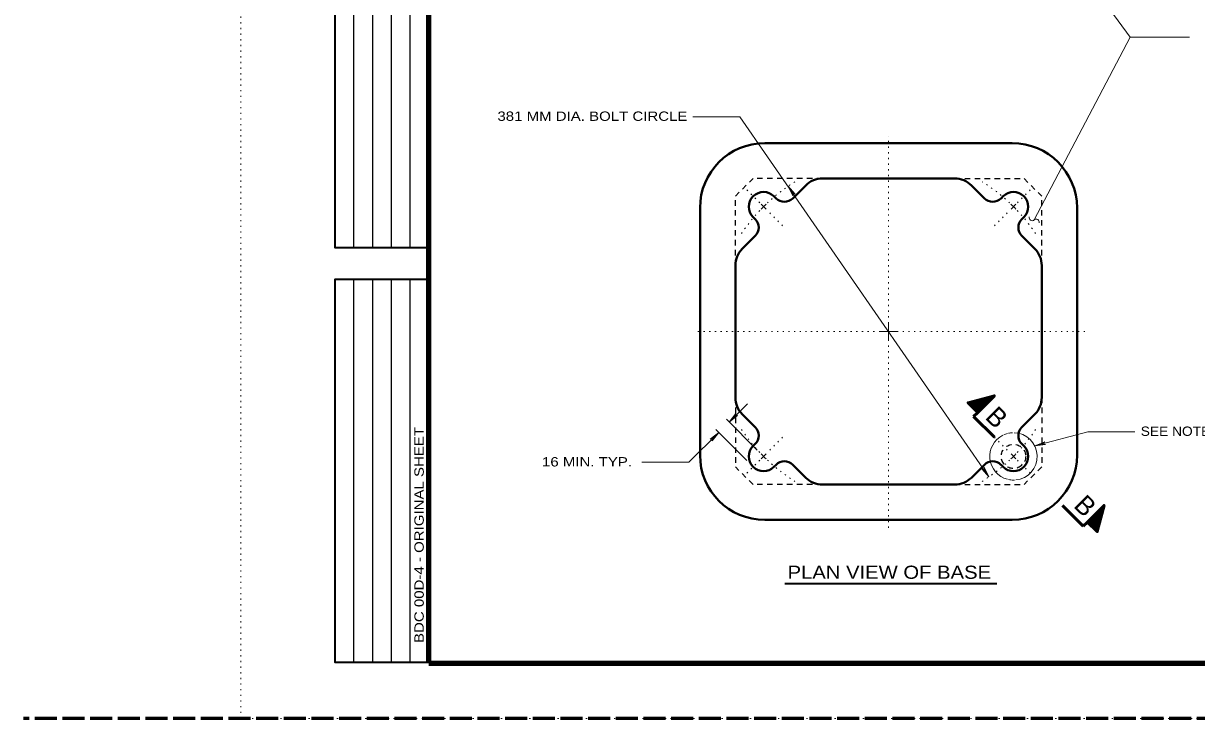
# Model space of a CAD drawing. Extents: x 312583 to 312854, y 144419 to 144597.
# Drawn here: x 312583.5 to 312678.9, y 144418.6 to 144475.2 of the extents above; entities that cross this region are included whole.
import ezdxf
from ezdxf.enums import TextEntityAlignment as Align

# ---------------------------------------------------------------- set-up
doc = ezdxf.new("R2010")
doc.units = 0
doc.header["$LTSCALE"] = 0.3
for name, pattern in [('DOTTED', [1.5, 0.3, -1.2]), ('LONG_DASHED', [7.5, 6, -1.5]), ('SHORT_DASHED', [2.7, 1.5, -1.2])]:
    doc.linetypes.add(name, pattern=pattern)
for name, color, linetype, lineweight in [('1', 7, 'Continuous', 40), ('2', 7, 'Continuous', 13), ('62', 7, 'DOTTED', 13), ('63', 7, 'LONG_DASHED', 60)]:
    doc.layers.add(name, color=color, linetype=linetype, lineweight=lineweight)

msp = doc.modelspace()

# ---------------------------------------------------------------- linework, layer by layer
at = {"layer": '1', "lineweight": 25}
for p, q in [((312610.4087, 144456.901), (312610.4087, 144488.1192)), ((312611.9315, 144456.901), (312611.9315, 144488.1192)), ((312613.4543, 144456.901), (312613.4543, 144488.1192)), ((312614.9772, 144456.901), (312614.9772, 144488.1192)), ((312610.4087, 144423.1446), (312610.4087, 144454.3629)), ((312611.9315, 144423.1446), (312611.9315, 144454.3629)), ((312613.4543, 144423.1446), (312613.4543, 144454.3629)), ((312614.9772, 144423.1446), (312614.9772, 144454.3629))]:
    msp.add_line(p, q, dxfattribs=at)
at = {"layer": '1'}
for p, q in [((312643.821, 144465.4263), (312653.8873, 144465.4263)), ((312663.946, 144465.4263), (312653.8873, 144465.4263)), ((312646.0903, 144460.9336), (312647.1483, 144461.9916)), ((312648.5053, 144462.5513), (312653.8873, 144462.5513)), ((312659.2693, 144462.5513), (312653.8873, 144462.5513)), ((312660.6187, 144461.9916), (312661.6767, 144460.9336)), ((312644.5647, 144461.1023), (312644.7333, 144460.9336)), ((312663.2023, 144461.1023), (312663.0337, 144460.9336)), ((312638.554, 144460.1516), (312638.554, 144450.0929)), ((312669.2207, 144460.1516), (312669.2207, 144450.0929)), ((312642.8703, 144459.4079), (312643.039, 144459.2393)), ((312664.8967, 144459.4079), (312664.728, 144459.2393)), ((312641.9887, 144456.8319), (312643.039, 144457.8823)), ((312664.728, 144457.8823), (312665.7783, 144456.8319)), ((312641.429, 144455.4749), (312641.429, 144450.0929)), ((312666.3457, 144455.4749), (312666.3457, 144450.0929)), ((312638.554, 144440.0266), (312638.554, 144450.0929)), ((312641.429, 144444.7109), (312641.429, 144450.0929)), ((312666.3457, 144444.7109), (312666.3457, 144450.0929)), ((312669.2207, 144440.0266), (312669.2207, 144450.0929)), ((312643.039, 144442.3036), (312641.9887, 144443.3539)), ((312665.7783, 144443.3539), (312664.728, 144442.3036)), ((312642.8703, 144440.7779), (312643.039, 144440.9466)), ((312664.8967, 144440.7779), (312664.728, 144440.9466)), ((312644.5647, 144439.0836), (312644.7333, 144439.2523)), ((312647.1483, 144438.1943), (312646.0903, 144439.2523)), ((312661.6767, 144439.2523), (312660.6187, 144438.1943)), ((312663.2023, 144439.0836), (312663.0337, 144439.2523)), ((312648.5053, 144437.6346), (312653.8873, 144437.6346)), ((312659.2693, 144437.6346), (312653.8873, 144437.6346)), ((312643.821, 144434.7596), (312653.8873, 144434.7596)), ((312663.946, 144434.7596), (312653.8873, 144434.7596))]:
    msp.add_line(p, q, dxfattribs=at)
at = {"layer": '1', "linetype": 'SHORT_DASHED', "lineweight": 25}
for p, q in [((312648.5053, 144462.5513), (312642.8627, 144462.5513)), ((312666.3457, 144455.4749), (312666.3457, 144461.1099)), ((312641.429, 144444.7109), (312641.429, 144439.0683)), ((312659.2693, 144437.6346), (312664.9043, 144437.6346))]:
    msp.add_line(p, q, dxfattribs=at)
at = {"layer": '1', "lineweight": 13}
for p, q in [((312645.7147, 144461.9149), (312646.1133, 144461.1406)), ((312645.7147, 144461.9149), (312646.2897, 144461.2633)), ((312646.1133, 144461.1406), (312646.052, 144461.4319)), ((312646.2897, 144461.2633), (312646.052, 144461.4319)), ((312643.9283, 144460.0519), (312643.522, 144460.4583)), ((312663.8463, 144460.0519), (312664.245, 144460.4583)), ((312643.9283, 144440.1339), (312643.522, 144439.7276)), ((312663.8463, 144440.1339), (312664.245, 144439.7276))]:
    msp.add_line(p, q, dxfattribs=at)
at = {"layer": '1', "linetype": 'DOTTED', "lineweight": 13}
for p, q in [((312643.407, 144460.5733), (312642.2877, 144461.6849)), ((312664.36, 144460.5733), (312665.4793, 144461.6849)), ((312645.27, 144458.7026), (312644.0357, 144459.9446)), ((312662.497, 144458.7026), (312663.7313, 144459.9446)), ((312645.27, 144441.4833), (312644.0357, 144440.2413)), ((312662.497, 144441.4833), (312663.7313, 144440.2413)), ((312643.407, 144439.6126), (312642.2877, 144438.4933)), ((312664.36, 144439.6126), (312665.4793, 144438.4933))]:
    msp.add_line(p, q, dxfattribs=at)
at = {"layer": '1', "lineweight": 158}
msp.add_line((312616.5, 144423.0846), (312849, 144423.0846), dxfattribs=at)
msp.add_lwpolyline([(312616.5, 144423.1446), (312616.5, 144585.0846), (312849, 144585.0846)], dxfattribs=at)
at = {"layer": '1', "lineweight": 35}
for points in [[(312616.5, 144456.901), (312608.8858, 144456.901), (312608.8858, 144488.1192), (312616.5, 144488.1192)], [(312616.5, 144423.1446), (312608.8858, 144423.1446), (312608.8858, 144454.3629), (312616.5, 144454.3629)]]:
    msp.add_lwpolyline(points, dxfattribs=at)
at = {"layer": '1', "linetype": 'SHORT_DASHED', "lineweight": 25}
for points in [[(312641.429, 144455.4749), (312641.429, 144461.1099), (312642.8627, 144462.5513)], [(312659.2693, 144462.5513), (312664.9043, 144462.5513), (312666.3457, 144461.1099)], [(312666.3457, 144444.7109), (312666.3457, 144439.0683), (312664.9043, 144437.6346)], [(312648.5053, 144437.6346), (312642.8627, 144437.6346), (312641.429, 144439.0683)]]:
    msp.add_lwpolyline(points, dxfattribs=at)
msp.add_circle((312664.0476, 144439.9269), 0.9909, dxfattribs=at)
at = {"layer": '1'}
for centre, radius, start, end in [((312643.821, 144460.1535), 5.2708, 90, 180), ((312663.946, 144460.1535), 5.2708, 0, 90), ((312648.5019, 144460.6327), 1.9167, 90, 135), ((312659.2651, 144460.6327), 1.9167, 45, 90), ((312643.7194, 144460.2551), 1.1979, 45, 225), ((312645.4138, 144461.6104), 0.9583, 225, 315), ((312662.3532, 144461.6104), 0.9583, 225, 315), ((312664.0476, 144460.2551), 1.1979, 315, 135), ((312642.3641, 144458.5608), 0.9583, 315, 45), ((312665.4029, 144458.5608), 0.9583, 135, 225), ((312643.3418, 144455.4726), 1.9167, 135, 180), ((312664.4252, 144455.4726), 1.9167, 0, 45), ((312643.3418, 144444.7094), 1.9167, 180, 225), ((312664.4252, 144444.7094), 1.9167, 315, 0), ((312642.3641, 144441.6213), 0.9583, 315, 45), ((312665.4029, 144441.6213), 0.9583, 135, 225), ((312643.821, 144440.0285), 5.2708, 180, 270), ((312643.7194, 144439.9269), 1.1979, 135, 315), ((312664.0476, 144439.9269), 1.1979, 225, 45), ((312663.946, 144440.0285), 5.2708, 270, 0), ((312645.4138, 144438.5716), 0.9583, 45, 135), ((312662.3532, 144438.5716), 0.9583, 45, 135), ((312648.5019, 144439.5493), 1.9167, 225, 270), ((312659.2651, 144439.5493), 1.9167, 270, 315)]:
    msp.add_arc(centre, radius, start, end, dxfattribs=at)
at = {"layer": '1', "linetype": 'DOTTED', "lineweight": 13}
for start, end in [(121.96733, 133.24434), (46.75566, 58.03267), (136.75599, 146.30781), (33.69219, 43.24401), (213.69219, 223.24401), (316.75599, 326.30781), (226.75566, 238.03268), (301.96733, 313.24434)]:
    msp.add_arc((312653.8835, 144450.091), 14.375, start, end, dxfattribs=at)
at = {"layer": '1', "lineweight": 13}
for centre, radius, start, end in [((312653.8835, 144450.091), 14.375, 133.83351, 136.1341), ((312653.8835, 144450.091), 14.375, 43.8659, 46.16649), ((312664.0476, 144439.9269), 1.9285, 92.27696, 101.90639), ((312664.0476, 144439.9269), 1.9285, 275.24598, 88.67448), ((312664.0476, 144439.9269), 1.9285, 116.79454, 255.14924), ((312664.0476, 144439.9269), 1.9285, 104.7083, 114.31631), ((312653.8835, 144450.091), 14.375, 223.8659, 226.16649), ((312653.8835, 144450.091), 14.375, 313.83351, 316.1341), ((312664.0476, 144439.9269), 1.9285, 257.50819, 264.13093), ((312664.0476, 144439.9269), 1.9285, 266.0607, 272.6285)]:
    msp.add_arc(centre, radius, start, end, dxfattribs=at)
at = {"layer": '2'}
for p, q in [((312673.5293, 144474.0513), (312668.178, 144481.4036)), ((312673.5293, 144474.0513), (312665.7247, 144459.1779)), ((312673.5293, 144474.0513), (312678.3517, 144474.0513)), ((312641.797, 144467.5806), (312637.9637, 144467.5806)), ((312641.797, 144467.5806), (312662.0523, 144438.2709)), ((312653.8873, 144450.0929), (312653.8873, 144450.8596)), ((312653.8873, 144450.0929), (312653.1207, 144450.0929)), ((312653.8873, 144450.0929), (312654.654, 144450.0929)), ((312653.8873, 144450.0929), (312653.8873, 144449.3263)), ((312640.9307, 144442.7253), (312642.418, 144444.2126)), ((312643.2077, 144440.4406), (312640.693, 144442.9553)), ((312640.9307, 144442.7253), (312641.4673, 144443.4076)), ((312640.9307, 144442.7253), (312641.613, 144443.2619)), ((312641.4673, 144443.4076), (312641.3447, 144443.1393)), ((312641.613, 144443.2619), (312641.3447, 144443.1393)), ((312637.6493, 144439.4439), (312640.0797, 144441.8743)), ((312640.0797, 144441.8743), (312639.3897, 144441.3376)), ((312640.0797, 144441.8743), (312639.543, 144441.1843)), ((312642.3567, 144439.5973), (312639.8497, 144442.1043)), ((312665.7783, 144440.7779), (312670.087, 144441.9356)), ((312670.087, 144441.9356), (312673.9203, 144441.9356)), ((312639.3897, 144441.3376), (312639.6657, 144441.4603)), ((312639.543, 144441.1843), (312639.6657, 144441.4603)), ((312665.7783, 144440.7779), (312666.591, 144441.1076)), ((312665.7783, 144440.7779), (312666.6447, 144440.9006)), ((312666.591, 144441.1076), (312666.3457, 144440.9313)), ((312666.6447, 144440.9006), (312666.3457, 144440.9313)), ((312637.6493, 144439.4439), (312633.816, 144439.4439)), ((312661.6537, 144439.0376), (312661.7227, 144438.7539)), ((312662.0523, 144438.2709), (312661.6537, 144439.0376)), ((312661.4773, 144438.9226), (312661.7227, 144438.7539)), ((312662.0523, 144438.2709), (312661.4773, 144438.9226))]:
    msp.add_line(p, q, dxfattribs=at)
at = {"layer": '2', "linetype": 'DOTTED'}
for p, q in [((312653.8873, 144451.2429), (312653.8873, 144465.9629)), ((312652.7373, 144450.0929), (312638.0787, 144450.0929)), ((312655.0373, 144450.0929), (312669.8417, 144450.0929)), ((312653.8873, 144448.9429), (312653.8873, 144433.9853))]:
    msp.add_line(p, q, dxfattribs=at)
at = {"layer": '2', "lineweight": 35}
for p, q in [((312661.9757, 144444.3429), (312661.876, 144444.7033)), ((312661.991, 144444.3583), (312661.899, 144444.7033)), ((312662.014, 144444.3813), (312661.922, 144444.7109)), ((312662.037, 144444.4043), (312661.945, 144444.7186)), ((312662.0523, 144444.4196), (312661.968, 144444.7186)), ((312662.0753, 144444.4426), (312661.9987, 144444.7339)), ((312662.0907, 144444.4579), (312662.014, 144444.7416)), ((312662.1137, 144444.4809), (312662.037, 144444.7416)), ((312662.1367, 144444.4963), (312662.06, 144444.7569)), ((312662.152, 144444.5193), (312662.083, 144444.7569)), ((312662.1673, 144444.5346), (312662.106, 144444.7646)), ((312662.1903, 144444.5576), (312662.1367, 144444.7723)), ((312662.2057, 144444.5729), (312662.152, 144444.7723)), ((312662.2287, 144444.5959), (312662.175, 144444.7799)), ((312662.2517, 144444.6189), (312662.2057, 144444.7876)), ((312662.267, 144444.6343), (312662.2287, 144444.7876)), ((312662.29, 144444.6573), (312662.244, 144444.7953)), ((312662.3053, 144444.6726), (312662.2747, 144444.8029)), ((312662.3207, 144444.6879), (312662.2977, 144444.8106)), ((312662.3437, 144444.7109), (312662.3207, 144444.8106)), ((312662.3667, 144444.7339), (312662.336, 144444.8259)), ((312662.3897, 144444.7569), (312662.3667, 144444.8336)), ((312662.405, 144444.7723), (312662.382, 144444.8336)), ((312662.428, 144444.7953), (312662.4127, 144444.8413)), ((312662.4433, 144444.8106), (312662.428, 144444.8489)), ((312662.4663, 144444.8336), (312662.451, 144444.8489)), ((312662.4817, 144444.8489), (312662.474, 144444.8643)), ((312660.3733, 144444.2739), (312660.3733, 144444.2969)), ((312660.4117, 144444.2433), (312660.3963, 144444.3046)), ((312660.45, 144444.2049), (312660.4193, 144444.3046)), ((312660.4807, 144444.1666), (312660.45, 144444.3123)), ((312660.519, 144444.1283), (312660.4653, 144444.3199)), ((312660.542, 144444.1053), (312660.4883, 144444.3199)), ((312660.5803, 144444.0669), (312660.5113, 144444.3353)), ((312660.6187, 144444.0363), (312660.542, 144444.3353)), ((312660.6493, 144443.9979), (312660.5573, 144444.3429)), ((312660.68, 144443.9673), (312660.588, 144444.3506)), ((312660.7183, 144443.9289), (312660.6033, 144444.3583)), ((312660.749, 144443.8983), (312660.634, 144444.3659)), ((312660.7797, 144443.8676), (312660.6493, 144444.3736)), ((312660.818, 144443.8293), (312660.6723, 144444.3736)), ((312660.8563, 144443.7986), (312660.6953, 144444.3889)), ((312660.887, 144443.7603), (312660.7183, 144444.3889)), ((312660.9253, 144443.7219), (312660.749, 144444.3889)), ((312660.956, 144443.6913), (312660.7643, 144444.4043)), ((312660.9867, 144443.6606), (312660.7873, 144444.4043)), ((312661.025, 144443.6299), (312660.818, 144444.4043)), ((312661.0633, 144443.5916), (312660.841, 144444.4196)), ((312661.0863, 144443.5609), (312660.8563, 144444.4196)), ((312661.1247, 144443.5226), (312660.887, 144444.4349)), ((312661.1553, 144443.5149), (312660.91, 144444.4349)), ((312661.1707, 144443.5379), (312660.933, 144444.4426)), ((312661.1937, 144443.5609), (312660.956, 144444.4503)), ((312661.209, 144443.5763), (312660.9713, 144444.4579)), ((312661.232, 144443.5993), (312661.002, 144444.4579)), ((312661.2473, 144443.6223), (312661.025, 144444.4733)), ((312661.2627, 144443.6453), (312661.0403, 144444.4733)), ((312661.2857, 144443.6529), (312661.0633, 144444.4809)), ((312661.3087, 144443.6759), (312661.094, 144444.4886)), ((312661.3317, 144443.6989), (312661.117, 144444.4886)), ((312661.347, 144443.7143), (312661.1323, 144444.4963)), ((312661.37, 144443.7373), (312661.163, 144444.5039)), ((312661.393, 144443.7603), (312661.186, 144444.5116)), ((312661.4083, 144443.7756), (312661.209, 144444.5193)), ((312661.4237, 144443.7986), (312661.232, 144444.5193)), ((312661.4467, 144443.8139), (312661.255, 144444.5346)), ((312661.4697, 144443.8293), (312661.278, 144444.5346)), ((312661.485, 144443.8523), (312661.301, 144444.5423)), ((312661.5003, 144443.8676), (312661.324, 144444.5499)), ((312661.5233, 144443.8906), (312661.3393, 144444.5576)), ((312661.5463, 144443.9136), (312661.37, 144444.5576)), ((312661.5617, 144443.9289), (312661.393, 144444.5729)), ((312661.5847, 144443.9519), (312661.4083, 144444.5729)), ((312661.6, 144443.9749), (312661.439, 144444.5883)), ((312661.623, 144443.9903), (312661.462, 144444.5883)), ((312661.6383, 144444.0056), (312661.485, 144444.5883)), ((312661.6613, 144444.0286), (312661.508, 144444.6036)), ((312661.6843, 144444.0516), (312661.531, 144444.6036)), ((312661.6997, 144444.0669), (312661.554, 144444.6113)), ((312661.7227, 144444.0899), (312661.577, 144444.6189)), ((312661.7457, 144444.1129), (312661.6, 144444.6266)), ((312661.761, 144444.1283), (312661.623, 144444.6266)), ((312661.784, 144444.1436), (312661.646, 144444.6419)), ((312661.7993, 144444.1666), (312661.669, 144444.6419)), ((312661.8147, 144444.1819), (312661.692, 144444.6496)), ((312661.8377, 144444.2049), (312661.715, 144444.6573)), ((312661.853, 144444.2203), (312661.738, 144444.6649)), ((312661.876, 144444.2433), (312661.761, 144444.6649)), ((312661.899, 144444.2663), (312661.784, 144444.6726)), ((312661.9143, 144444.2816), (312661.807, 144444.6803)), ((312661.9373, 144444.3046), (312661.83, 144444.6803)), ((312661.9527, 144444.3199), (312661.853, 144444.6879)), ((312670.6467, 144435.1659), (312671.1757, 144435.0203)), ((312670.6697, 144435.1889), (312671.1833, 144435.0433)), ((312670.685, 144435.2043), (312671.1833, 144435.0663)), ((312670.7003, 144435.2273), (312671.1987, 144435.0893)), ((312670.7233, 144435.2426), (312671.1987, 144435.1123)), ((312670.7387, 144435.2579), (312671.2063, 144435.1353)), ((312670.7617, 144435.2809), (312671.214, 144435.1583)), ((312670.777, 144435.2963), (312671.2217, 144435.1813)), ((312670.8, 144435.3193), (312671.2217, 144435.2043)), ((312670.823, 144435.3423), (312671.2293, 144435.2273)), ((312670.8383, 144435.3576), (312671.237, 144435.2503)), ((312670.8613, 144435.3806), (312671.237, 144435.2733)), ((312670.8767, 144435.3959), (312671.2447, 144435.2963)), ((312670.8997, 144435.4189), (312671.26, 144435.3193)), ((312670.915, 144435.4343), (312671.26, 144435.3423)), ((312670.938, 144435.4573), (312671.2677, 144435.3653)), ((312670.961, 144435.4803), (312671.2753, 144435.3883)), ((312670.9763, 144435.4956), (312671.2753, 144435.4113)), ((312670.9993, 144435.5186), (312671.2907, 144435.4419)), ((312671.0147, 144435.5339), (312671.2983, 144435.4573)), ((312671.0377, 144435.5569), (312671.2983, 144435.4803)), ((312671.053, 144435.5799), (312671.3137, 144435.5033)), ((312671.076, 144435.5953), (312671.3137, 144435.5263)), ((312671.0913, 144435.6106), (312671.3213, 144435.5493)), ((312671.1143, 144435.6336), (312671.329, 144435.5799)), ((312671.1297, 144435.6489), (312671.329, 144435.5953)), ((312671.1527, 144435.6719), (312671.3367, 144435.6183)), ((312671.1757, 144435.6949), (312671.3443, 144435.6489)), ((312671.191, 144435.7103), (312671.3443, 144435.6719)), ((312671.214, 144435.7333), (312671.352, 144435.6873)), ((312671.2293, 144435.7486), (312671.3597, 144435.7179)), ((312671.2447, 144435.7639), (312671.3673, 144435.7409)), ((312671.2677, 144435.7869), (312671.3673, 144435.7639)), ((312671.2907, 144435.8099), (312671.3827, 144435.7793)), ((312671.3137, 144435.8329), (312671.3903, 144435.8099)), ((312671.329, 144435.8483), (312671.3903, 144435.8253)), ((312671.352, 144435.8713), (312671.398, 144435.8559)), ((312671.3673, 144435.8866), (312671.4057, 144435.8713)), ((312671.3903, 144435.9096), (312671.4057, 144435.8943)), ((312671.4057, 144435.9249), (312671.421, 144435.9173)), ((312670.0717, 144434.5986), (312670.9917, 144434.3533)), ((312670.0793, 144434.5679), (312670.9917, 144434.3303)), ((312670.0947, 144434.6139), (312670.9993, 144434.3763)), ((312670.1177, 144434.6369), (312671.007, 144434.3993)), ((312670.1177, 144434.5296), (312670.9763, 144434.2996)), ((312670.133, 144434.6523), (312671.0147, 144434.4146)), ((312670.1483, 144434.5066), (312670.9763, 144434.2843)), ((312670.156, 144434.6753), (312671.0147, 144434.4453)), ((312670.179, 144434.6906), (312671.03, 144434.4683)), ((312670.1867, 144434.4683), (312670.961, 144434.2613)), ((312670.202, 144434.7059), (312671.03, 144434.4836)), ((312670.2097, 144434.7289), (312671.0377, 144434.5066)), ((312670.2173, 144434.4299), (312670.961, 144434.2306)), ((312670.2327, 144434.7519), (312671.0453, 144434.5373)), ((312670.248, 144434.3993), (312670.961, 144434.2076)), ((312670.2557, 144434.7749), (312671.0453, 144434.5603)), ((312670.271, 144434.7903), (312671.053, 144434.5756)), ((312670.2787, 144434.3686), (312670.9457, 144434.1923)), ((312670.294, 144434.8133), (312671.0607, 144434.6063)), ((312670.317, 144434.8363), (312671.0683, 144434.6293)), ((312670.317, 144434.3303), (312670.9457, 144434.1616)), ((312670.3323, 144434.8516), (312671.076, 144434.6523)), ((312670.3553, 144434.8669), (312671.076, 144434.6753)), ((312670.3553, 144434.2996), (312670.9457, 144434.1386)), ((312670.3707, 144434.8899), (312671.0913, 144434.6983)), ((312670.386, 144434.9129), (312671.0913, 144434.7213)), ((312670.386, 144434.2613), (312670.9303, 144434.1156)), ((312670.409, 144434.9283), (312671.099, 144434.7443)), ((312670.4243, 144434.9436), (312671.1067, 144434.7673)), ((312670.4243, 144434.2229), (312670.9303, 144434.0926)), ((312670.4473, 144434.9666), (312671.1143, 144434.7826)), ((312670.4703, 144434.9896), (312671.1143, 144434.8133)), ((312670.4857, 144435.0049), (312671.1297, 144434.8363)), ((312670.5087, 144435.0279), (312671.1297, 144434.8516)), ((312670.5317, 144435.0433), (312671.145, 144434.8823)), ((312670.547, 144435.0663), (312671.145, 144434.9053)), ((312670.5623, 144435.0816), (312671.145, 144434.9283)), ((312670.5853, 144435.1046), (312671.1603, 144434.9513)), ((312670.6083, 144435.1276), (312671.1603, 144434.9743)), ((312670.6237, 144435.1429), (312671.168, 144434.9973)), ((312670.455, 144434.1923), (312670.9227, 144434.0773)), ((312670.4857, 144434.1616), (312670.915, 144434.0466)), ((312670.524, 144434.1233), (312670.9073, 144434.0313)), ((312670.5547, 144434.0926), (312670.8997, 144434.0006)), ((312670.593, 144434.0619), (312670.892, 144433.9853)), ((312670.6237, 144434.0236), (312670.892, 144433.9546)), ((312670.662, 144433.9853), (312670.8767, 144433.9316)), ((312670.685, 144433.9623), (312670.8767, 144433.9086)), ((312670.7233, 144433.9239), (312670.869, 144433.8933)), ((312670.7617, 144433.8933), (312670.8613, 144433.8626)), ((312670.8, 144433.8549), (312670.8613, 144433.8396)), ((312670.8307, 144433.8166), (312670.8537, 144433.8166)), ((312645.4543, 144429.5693), (312662.69, 144429.5693))]:
    msp.add_line(p, q, dxfattribs=at)
at = {"layer": '2', "lineweight": 53}
for p, q in [((312661.14, 144443.5073), (312660.8027, 144443.1699)), ((312662.497, 144441.4833), (312660.8027, 144443.1699)), ((312668.04, 144435.9403), (312669.7267, 144434.2459)), ((312670.064, 144434.5833), (312669.7267, 144434.2459))]:
    msp.add_line(p, q, dxfattribs=at)
for points in [[(312661.14, 144443.5073), (312660.358, 144444.2969), (312662.497, 144444.8643)], [(312670.064, 144434.5833), (312670.8537, 144433.8013), (312671.421, 144435.9403)]]:
    msp.add_lwpolyline(points, close=True, dxfattribs=at)
at = {"layer": '2'}
for centre, start, end in [((312665.5604, 144459.3523), 163.93536, 313.93536), ((312665.8927, 144459.0074), 343.93536, 133.93536)]:
    msp.add_arc(centre, 0.2395, start, end, dxfattribs=at)
at = {"layer": '62'}
msp.add_line((312601.2, 144418.5846), (312601.2, 144596.7846), dxfattribs=at)
msp.add_lwpolyline([(312601.2, 144418.5846), (312853.5, 144418.5846), (312853.5, 144596.7846)], dxfattribs=at)
at = {"layer": '63'}
msp.add_line((312851.75, 144418.5846), (312583.526, 144418.5846), dxfattribs=at)

# ---------------------------------------------------------------- texts
at = {"layer": '1', "width": 1.2}
msp.add_text('BDC 00D-4 - ORIGINAL SHEET', height=0.7614, rotation=90, dxfattribs=at).set_placement((312616.0832, 144424.7374))
at = {"layer": '2'}
for s, width, p in [('381 MM DIA. BOLT CIRCLE', 1.2, (312622.0751, 144467.2416)), ('SEE NOTE 12', 1.1, (312674.3957, 144441.5966)), ('16 MIN. TYP.', 1.2, (312625.7004, 144439.1049))]:
    msp.add_text(s, height=0.76, dxfattribs=dict(at, width=width)).set_placement(p)
for height, p in [(1.534, (312662.1464, 144442.5699)), (1.533, (312669.3454, 144435.3709))]:
    msp.add_text('B', height=height, rotation=315, dxfattribs=at).set_placement(p, align=Align.CENTER)
at = {"layer": '2', "width": 1.15}
msp.add_text('PLAN VIEW OF BASE', height=1.07, dxfattribs=at).set_placement((312653.9485, 144429.9612), align=Align.CENTER)

doc.saveas('drawing.dxf')
